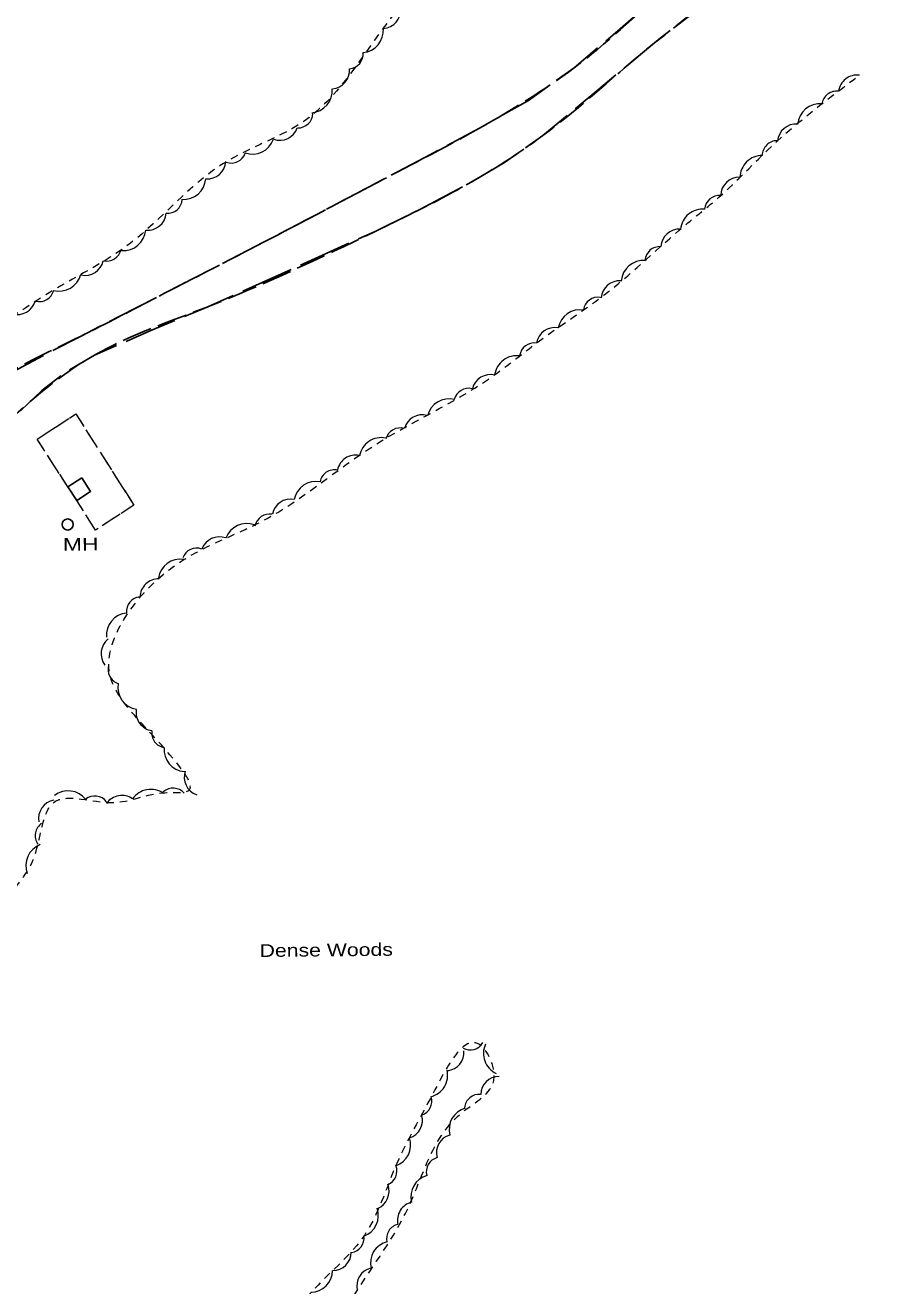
# Model space of a CAD drawing. Extents: x 2362213 to 2366494, y 6968794 to 6978110.
# Drawn here: x 2364719.3 to 2365039.4, y 6972789.5 to 6973266.2 of the extents above; entities that cross this region are included whole.
import ezdxf

# ---------------------------------------------------------------- set-up
doc = ezdxf.new("R2010")
doc.units = 0
doc.header["$LTSCALE"] = 1.9
for name, pattern in [('LONG_DASHED', [7.5, 6, -1.5]), ('MEDIUM_DASHED', [4.5, 3, -1.5]), ('SHORT_DASHED', [2.7, 1.5, -1.2])]:
    doc.linetypes.add(name, pattern=pattern)
for name, color, linetype, lineweight in [('14', 7, 'Continuous', 13), ('20', 7, 'Continuous', 25), ('23', 7, 'Continuous', 25), ('29', 7, 'Continuous', 13), ('3', 7, 'Continuous', 25)]:
    doc.layers.add(name, color=color, linetype=linetype, lineweight=lineweight)

msp = doc.modelspace()

# ---------------------------------------------------------------- linework, layer by layer
at = {"layer": '14'}
for p, q in [((2364727.639, 6973112.131), (2364734.348, 6973116.495)), ((2364742.28, 6973113.21), (2364746.574, 6973106.461)), ((2364732.207, 6973096.634), (2364727.892, 6973103.373)), ((2364747.65, 6973104.771), (2364751.944, 6973098.023)), ((2364753.021, 6973096.332), (2364757.305, 6973089.582)), ((2364735.445, 6973091.584), (2364733.283, 6973094.954)), ((2364741.231, 6973082.709), (2364738.894, 6973086.457)), ((2364755.274, 6973081.303), (2364748.555, 6973076.959))]:
    msp.add_line(p, q, dxfattribs=at)
at = {"layer": '14', "linetype": 'MEDIUM_DASHED'}
msp.add_lwpolyline([(2364735.445, 6973091.584), (2364723.852, 6973109.665), (2364738.472, 6973119.185), (2364760.442, 6973084.642), (2364745.881, 6973075.224), (2364738.894, 6973086.457)], dxfattribs=at)
at = {"layer": '14'}
for points in [[(2364736.027, 6973117.591), (2364738.472, 6973119.185), (2364741.204, 6973114.9)], [(2364726.816, 6973105.053), (2364723.852, 6973109.665), (2364725.959, 6973111.035)], [(2364758.381, 6973087.893), (2364760.442, 6973084.642), (2364756.954, 6973082.389)], [(2364746.875, 6973075.874), (2364745.881, 6973075.224), (2364742.287, 6973081.009)]]:
    msp.add_lwpolyline(points, dxfattribs=at)
at = {"layer": '20'}
msp.add_circle((2364735.4, 6973077.383), 2.1, dxfattribs=at)
at = {"layer": '23'}
msp.add_lwpolyline([(2364740.753, 6973095.025), (2364735.445, 6973091.584), (2364738.894, 6973086.457), (2364744.051, 6973089.896)], close=True, dxfattribs=at)
at = {"layer": '29'}
for centre, radius, start, end in [((2364854.244, 6973271.899), 7.048, 274.62144, 4.62144), ((2364846.308, 6973264.237), 8.454, 274.70301, 4.70301), ((2364841.502, 6973255.347), 5.632, 274.70301, 4.70301), ((2364834.928, 6973249.137), 7.048, 274.66082, 4.66082), ((2365033.819, 6973240.295), 7.032, 82.47796, 172.47796), ((2364826.999, 6973241.479), 8.454, 274.66082, 4.66082), ((2365026.095, 6973235.625), 5.619, 82.47796, 172.47796), ((2365019.848, 6973228.073), 8.434, 85.42278, 175.42278), ((2364822.421, 6973232.949), 5.632, 268.58797, 358.58797), ((2364815.546, 6973229.685), 7.048, 250.88086, 340.88086), ((2365010.814, 6973221.802), 7.032, 85.42278, 175.42278), ((2364805.203, 6973225.874), 8.454, 250.88086, 340.88086), ((2365003.586, 6973216.877), 5.619, 89.3677, 179.3677), ((2364797.215, 6973219.683), 5.632, 250.88086, 340.88086), ((2364997.987, 6973208.492), 8.434, 89.3677, 179.3677), ((2364788.155, 6973215.092), 7.048, 266.01926, 356.01926), ((2364779.165, 6973208.713), 8.454, 266.01926, 356.01926), ((2364989.301, 6973201.641), 7.032, 88.70439, 178.70439), ((2364981.784, 6973196.14), 5.619, 84.76733, 174.76733), ((2364773.102, 6973200.707), 5.632, 265.16282, 355.16282), ((2364975.511, 6973188.229), 8.434, 84.6202, 174.6202), ((2364765.587, 6973195.669), 7.048, 265.16282, 355.16282), ((2364756.503, 6973189.425), 8.454, 265.16282, 355.16282), ((2364966.637, 6973182.033), 7.032, 86.38687, 176.38687), ((2364959.249, 6973176.848), 5.619, 86.38687, 176.38687), ((2364741.964, 6973178.607), 7.048, 257.68069, 347.68069), ((2364750.071, 6973182.624), 5.632, 257.68069, 347.68069), ((2364953.075, 6973168.782), 8.434, 85.44628, 175.44628), ((2364732.167, 6973174.081), 8.454, 255.12026, 345.12026), ((2364944.044, 6973162.508), 7.032, 85.44628, 175.44628), ((2364724.659, 6973167.316), 5.632, 255.12026, 345.12026), ((2364935.972, 6973157.721), 5.619, 81.10285, 171.10285), ((2364716.382, 6973163.794), 7.048, 254.37647, 344.37647), ((2364929.119, 6973150.176), 8.434, 79.9951, 169.9951), ((2364919.533, 6973144.788), 7.032, 79.9951, 169.9951), ((2364911.829, 6973140.413), 5.619, 82.13663, 172.13663), ((2364905.164, 6973132.788), 8.434, 81.65186, 171.65186), ((2364895.207, 6973127.023), 7.032, 75.89364, 165.89364), ((2364879.599, 6973116.421), 8.434, 75.89364, 165.89364), ((2364886.998, 6973123.271), 5.619, 75.89364, 165.89364), ((2364869.451, 6973111.825), 7.032, 74.41391, 164.41391), ((2364854.006, 6973101.812), 8.434, 78.80786, 168.80786), ((2364861.148, 6973108.285), 5.619, 74.41391, 164.41391), ((2364844.31, 6973096.624), 7.032, 78.80786, 168.80786), ((2364836.302, 6973092.459), 5.619, 78.80786, 168.80786), ((2364829.34, 6973085.232), 8.434, 79.37551, 169.37551), ((2364819.696, 6973079.948), 7.032, 79.37551, 169.37551), ((2364803.1, 6973069.322), 8.434, 69.90764, 159.90764), ((2364811.73, 6973075.704), 5.619, 79.37551, 169.37551), ((2364792.718, 6973065.696), 7.032, 69.90764, 159.90764), ((2364784.163, 6973062.82), 5.619, 69.90764, 159.90764), ((2364778.016, 6973055.844), 8.434, 81.16091, 171.16091), ((2364769.77, 6973049.805), 7.032, 88.6741, 178.6741), ((2364763.181, 6973044.399), 5.619, 95.20529, 185.20529), ((2364758.463, 6973035.489), 8.434, 95.20529, 185.20529), ((2364755.058, 6973028.538), 7.032, 127.68383, 217.68383), ((2364756.257, 6973022.598), 5.619, 162.94548, 252.94548), ((2364762.799, 6973015.827), 8.434, 170.37483, 260.37483), ((2364768.274, 6973006.39), 7.032, 171.28741, 261.28741), ((2364772.782, 6972998.571), 5.619, 171.28741, 261.28741), ((2364780.254, 6972992.323), 8.434, 175.0795, 265.0795), ((2364786.507, 6972981.787), 7.032, 160.56676, 250.56676), ((2364766.838, 6972968.778), 8.434, 55.21619, 145.21619), ((2364775.254, 6972972.059), 5.619, 41.18106, 131.18106), ((2364731.389, 6972966.18), 7.032, 99.99083, 189.99083), ((2364735.582, 6972968.227), 8.434, 37.86523, 127.86523), ((2364745.63, 6972969.064), 5.619, 37.86523, 127.86523), ((2364755.879, 6972967.902), 7.032, 55.23697, 145.23697), ((2364728.72, 6972959.718), 5.619, 124.38444, 214.38444), ((2364727.995, 6972948.433), 8.434, 110.73963, 200.73962), ((2364887.589, 6972884.223), 5.522, 240.29136, 330.29136), ((2364878.345, 6972877.732), 6.91, 275.68031, 5.68031), ((2364900.86, 6972877.345), 8.288, 154.91593, 244.91593), ((2364870.764, 6972869.07), 8.288, 283.41549, 13.41549), ((2364898.466, 6972861.765), 6.91, 89.69203, 179.69203), ((2364867.576, 6972859.357), 5.522, 287.24284, 17.24284), ((2364890.968, 6972856.399), 5.522, 85.15642, 175.15642), ((2364862.605, 6972852.01), 6.91, 287.24284, 17.24284), ((2364887.915, 6972848.717), 8.288, 105.64642, 195.64642), ((2364856.78, 6972842.77), 8.288, 288.62606, 18.62606), ((2364881.717, 6972839.871), 6.91, 105.64642, 195.64642), ((2364854.362, 6972832.918), 5.522, 291.71598, 21.71598), ((2364876.497, 6972832.645), 5.522, 105.03947, 195.03947), ((2364873.425, 6972823.225), 8.288, 105.03947, 195.03947), ((2364849.98, 6972825.207), 6.91, 291.71598, 21.71598), ((2364866.982, 6972814.345), 6.91, 103.11224, 193.11224), ((2364844.561, 6972816.068), 8.288, 289.71306, 19.71306), ((2364861.495, 6972807.376), 5.522, 103.11224, 193.11224), ((2364841.91, 6972807.519), 5.522, 278.61399, 8.61399), ((2364858.142, 6972798.091), 8.288, 103.50006, 193.50006), ((2364835.64, 6972802.19), 6.91, 269.95058, 359.95058), ((2364851.617, 6972789.483), 6.91, 103.50006, 193.50006), ((2364827.28, 6972795.35), 8.288, 269.95058, 359.95058)]:
    msp.add_arc(centre, radius, start, end, dxfattribs=at)
at = {"layer": '29', "linetype": 'SHORT_DASHED'}
for points in [[(2365037.9, 6973445.442), (2365023.867, 6973443.538), (2364999.858, 6973421.228), (2364985.979, 6973383.353), (2364961.682, 6973351.471), (2364919.882, 6973332.353), (2364891.333, 6973307.82), (2364852.932, 6973262.692), (2364825.656, 6973230.551), (2364794.303, 6973213.861), (2364759.119, 6973183.714), (2364726.228, 6973163.641), (2364691.145, 6973149.085), (2364672.071, 6973167.265), (2364648.319, 6973219.931), (2364641.358, 6973236.796), (2364636.841, 6973275.345), (2364632.955, 6973317.91), (2364633.839, 6973353.19), (2364642.437, 6973385.983), (2364662.883, 6973404.408), (2364697.318, 6973388.316), (2364703.318, 6973386.163), (2364702.987, 6973394.75), (2364679.658, 6973414.499), (2364653.986, 6973435.595), (2364631.869, 6973467.706), (2364629.652, 6973504.117), (2364635.711, 6973530.496), (2364651.373, 6973540.755), (2364660.079, 6973545.508), (2364682.24, 6973549.68), (2364708.599, 6973552.041), (2364711.122, 6973554.875), (2364716.112, 6973558.002), (2364707.645, 6973571.412), (2364721.228, 6973584.753), (2364740.489, 6973576.385), (2364750.789, 6973581.634), (2364740.985, 6973597.751), (2364740.587, 6973615.388), (2364760.636, 6973614.609), (2364784.012, 6973604.631), (2364796.396, 6973587.489), (2364771.96, 6973567.955), (2364755.353, 6973559.226), (2364752.077, 6973553.565), (2364768.906, 6973549.535), (2364787.761, 6973550.074), (2364820.279, 6973547.324), (2364834.075, 6973543.615), (2364850.314, 6973529.109), (2364856.022, 6973511.533), (2364865.139, 6973488.768), (2364883.65, 6973494.005), (2364902.284, 6973485.282), (2364914.875, 6973474.651), (2364943.698, 6973478.866), (2364973.379, 6973493.459), (2365009.261, 6973508.222), (2365035.34, 6973515.84), (2365039.397, 6973516.189)], [(2364601.05, 6972756.458), (2364599.977, 6972788.251), (2364608.381, 6972813.072), (2364624.698, 6972829.287), (2364642.258, 6972836.636), (2364662.512, 6972830.017), (2364674.393, 6972816.451), (2364685.962, 6972823.86), (2364674.342, 6972846.99), (2364675.578, 6972876.785), (2364692.215, 6972891.883), (2364704.288, 6972903.099), (2364707.474, 6972921.45), (2364713.466, 6972937.007), (2364722.22, 6972950.312), (2364730.777, 6972972.705), (2364752.072, 6972972.247), (2364772.847, 6972975.995), (2364780.922, 6972976.642), (2364773.1, 6972991.448), (2364750.938, 6973024.179), (2364772.633, 6973059.387), (2364809.39, 6973078.898), (2364851.411, 6973107.339), (2364894.464, 6973132.35), (2364912.923, 6973146.208), (2364939.902, 6973165.486), (2364968.239, 6973190.047), (2364981.633, 6973201.164), (2365001.511, 6973220.384), (2365034.688, 6973247.201)], [(2364820.191, 6972745.846), (2364826.67, 6972756.497), (2364844.459, 6972787.119), (2364864.087, 6972818.907), (2364884.802, 6972855.286), (2364896.555, 6972867.678), (2364890.557, 6972881.002), (2364873.25, 6972861.786), (2364859.123, 6972834.14), (2364847.693, 6972808.809), (2364828.866, 6972788.55), (2364813.83, 6972768.036), (2364802.827, 6972747.23)]]:
    msp.add_spline(points, degree=3, dxfattribs=at)
at = {"layer": '3'}
for p, q in [((2364823.47, 6973175.446), (2364841.683, 6973183.7)), ((2364801.563, 6973165.638), (2364819.826, 6973173.792))]:
    msp.add_line(p, q, dxfattribs=at)
for points in [[(2364964.415, 6973265.023), (2364974.759, 6973272.971), (2364980.177, 6973277.334)], [(2364953.995, 6973273.204), (2364944.246, 6973264.821), (2364938.799, 6973260.199)], [(2364945.768, 6973249.924), (2364957.226, 6973259.495), (2364961.248, 6973262.583)], [(2364935.753, 6973257.61), (2364926.846, 6973250.044), (2364920.081, 6973245.22)], [(2364927.303, 6973234.589), (2364936.202, 6973241.943), (2364942.692, 6973247.365)], [(2364916.822, 6973242.898), (2364909.571, 6973237.73), (2364899.924, 6973232.258)], [(2364896.443, 6973230.285), (2364891.08, 6973227.243), (2364878.873, 6973220.726)], [(2364908.422, 6973219.797), (2364915.068, 6973224.471), (2364924.217, 6973232.039)], [(2364875.341, 6973218.842), (2364870.365, 6973216.186), (2364857.679, 6973209.465)], [(2364888.143, 6973207.004), (2364900.516, 6973214.233), (2364905.154, 6973217.496)], [(2364854.147, 6973207.591), (2364849.608, 6973205.197), (2364836.454, 6973198.261)], [(2364866.98, 6973195.692), (2364868.503, 6973196.426), (2364884.682, 6973205.001)], [(2364832.912, 6973196.397), (2364829.788, 6973194.747), (2364815.199, 6973187.109)], [(2364845.327, 6973185.356), (2364851.601, 6973188.196), (2364863.386, 6973193.937)], [(2364811.658, 6973185.245), (2364809.946, 6973184.348), (2364793.893, 6973176.045)], [(2364790.341, 6973174.201), (2364789.744, 6973173.895), (2364772.547, 6973165.062)], [(2364768.984, 6973163.238), (2364754.862, 6973156.002), (2364751.18, 6973154.127)], [(2364779.563, 6973156.047), (2364788.32, 6973159.721), (2364797.908, 6973164.003)], [(2364757.492, 6973146.637), (2364766.893, 6973150.737), (2364775.878, 6973154.502)], [(2364747.617, 6973152.313), (2364740.204, 6973148.522), (2364729.834, 6973143.164)], [(2364736.073, 6973135.912), (2364745.541, 6973141.434), (2364753.827, 6973145.043)], [(2364726.281, 6973141.33), (2364724.32, 6973140.321), (2364708.589, 6973132.011)], [(2364717.698, 6973120.548), (2364725.667, 6973128.053), (2364732.835, 6973133.581)]]:
    msp.add_lwpolyline(points, dxfattribs=at)
at = {"layer": '3', "linetype": 'LONG_DASHED'}
for points in [[(2364586.418, 6973732.225), (2364587.303, 6973681.251), (2364585.662, 6973600.522), (2364582.985, 6973495.062), (2364577.659, 6973423.248), (2364568.544, 6973352.398), (2364564.637, 6973277.537), (2364558.912, 6973186.489), (2364556.952, 6973116.226), (2364559.351, 6973045.936), (2364565.972, 6973011.287), (2364580.244, 6972998.572), (2364598.847, 6972995.149), (2364623.128, 6973000.381), (2364639.74, 6973009.769), (2364657.902, 6973019.033), (2364663.899, 6973045.691), (2364668.807, 6973072.129), (2364690.41, 6973094.006), (2364708.084, 6973111.485), (2364745.541, 6973141.434), (2364788.32, 6973159.721), (2364851.601, 6973188.196), (2364885.129, 6973205.245), (2364915.068, 6973224.471), (2364957.226, 6973259.495), (2364991.978, 6973286.847), (2365029.676, 6973321.948), (2365035.414, 6973327.423)], [(2365035.821, 6973346.657), (2365009.612, 6973321.197), (2364961.545, 6973279.697), (2364926.846, 6973250.044), (2364891.08, 6973227.243), (2364849.608, 6973205.197), (2364809.946, 6973184.348), (2364769.512, 6973163.503), (2364740.204, 6973148.522), (2364708.509, 6973131.97), (2364679.625, 6973111.234), (2364659.133, 6973099.798), (2364638.529, 6973090.722), (2364633.002, 6973061.988), (2364632.179, 6973043.439), (2364631.535, 6973024.962), (2364628.009, 6973014.918), (2364611.461, 6973008.45), (2364595.457, 6973014.018), (2364585.424, 6973021.643), (2364575.434, 6973049.999), (2364575.353, 6973067.879), (2364576.383, 6973108.941), (2364575.253, 6973166.653), (2364576.666, 6973250.3), (2364579.404, 6973334.51), (2364592.381, 6973455.7), (2364598.173, 6973557.429), (2364599.069, 6973657.462), (2364599.948, 6973705.963), (2364599.449, 6973730.979)]]:
    msp.add_spline(points, degree=3, dxfattribs=at)

# ---------------------------------------------------------------- texts
at = {"layer": '20', "width": 1.35}
msp.add_text('  MH', height=4.8, rotation=0.546, dxfattribs=at).set_placement((2364728.785, 6973067.39))
at = {"layer": '29', "width": 1.25}
msp.add_text('Dense Woods', height=4.8, rotation=0.546, dxfattribs=at).set_placement((2364807.972, 6972913.847))

doc.saveas('drawing.dxf')
